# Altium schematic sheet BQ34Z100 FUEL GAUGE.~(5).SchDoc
size A3; SheetNumber: 13; SheetTotal: 14
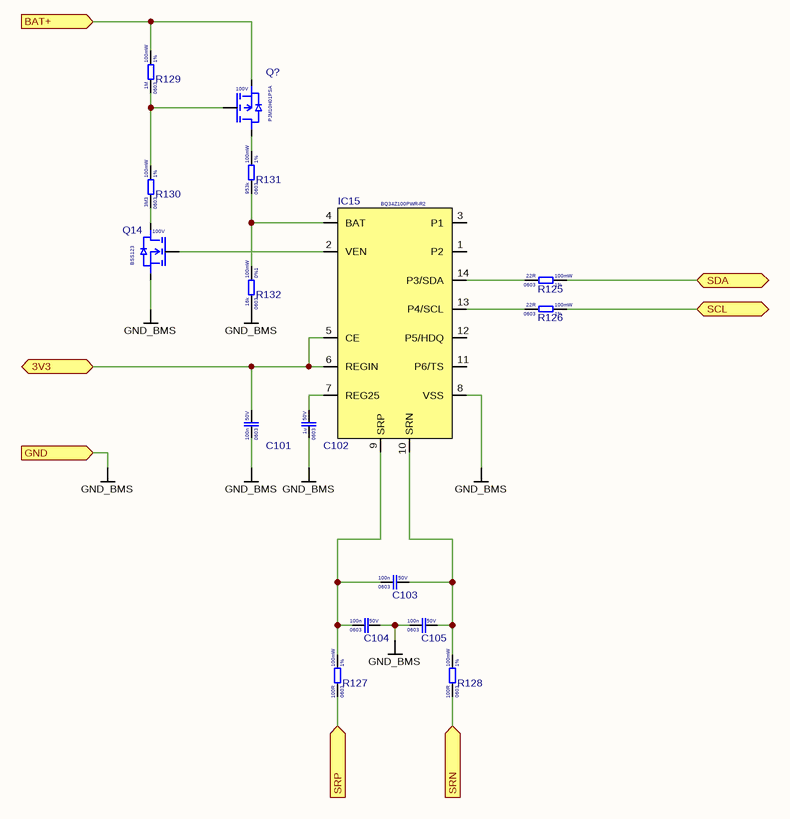
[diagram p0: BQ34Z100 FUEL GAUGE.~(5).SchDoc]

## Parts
C101  Voltage Rating: 50V  Case Code (Imperial): 0603  Capacitance: 100n  [CAP 0603]  (hidden comment: CC0603KRX7R9BB104)
C102  Voltage Rating: 50V  Case Code (Imperial): 0603  Capacitance: 1u  [CAP 0603]  (hidden comment: CL10A105KB8NNNC)
C103  Voltage Rating: 50V  Case Code (Imperial): 0603  Capacitance: 100n  [CAP 0603]  (hidden comment: CC0603KRX7R9BB104)
C104  Voltage Rating: 50V  Case Code (Imperial): 0603  Capacitance: 100n  [CAP 0603]  (hidden comment: CC0603KRX7R9BB104)
C105  Voltage Rating: 50V  Case Code (Imperial): 0603  Capacitance: 100n  [CAP 0603]  (hidden comment: CC0603KRX7R9BB104)
IC15  BQ34Z100PWR-R2  [TSSOP-14]
Q14  Voltage: 100V  [SOT-23 GSD]  (hidden comment: BSS123)
Q?  Voltage: 100V  [SOT-23 GSD]  (hidden comment: PJM10H01PSA)
R125  Resistance Tolerance: 1%  Resistance: 22R  Power Rating: 100mW  Case Code (Imperial): 0603  [RES_0603]  (hidden comment: 0603WAF220JT5E)
R126  Resistance Tolerance: 1%  Resistance: 22R  Power Rating: 100mW  Case Code (Imperial): 0603  [RES_0603]  (hidden comment: 0603WAF220JT5E)
R127  Resistance Tolerance: 1%  Resistance: 100R  Power Rating: 100mW  Case Code (Imperial): 0603  [RES_0603]  (hidden comment: 0603WAF1000T5E)
R128  Resistance Tolerance: 1%  Resistance: 100R  Power Rating: 100mW  Case Code (Imperial): 0603  [RES_0603]  (hidden comment: 0603WAF1000T5E)
R129  Resistance Tolerance: 1%  Resistance: 1M  Power Rating: 100mW  Case Code (Imperial): 0603  [RES_0603]  (hidden comment: 0603WAF1004T5E)
R130  Resistance Tolerance: 1%  Resistance: 3M3  Power Rating: 100mW  Case Code (Imperial): 0603  [RES_0603]  (hidden comment: 0603WAF3304T5E)
R131  Resistance Tolerance: 1%  Resistance: 953k  Power Rating: 100mW  Case Code (Imperial): 0603  [RES_0603]  (hidden comment: AC0603FR-07953KL)
R132  Resistance Tolerance: 0%1  Resistance: 16k  Power Rating: 100mW  Case Code (Imperial): 0603  [RES_0603]  (hidden comment: RT0603BRD0716KL)

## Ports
3V3 (bidir, see BMS[4C], 5V to 3V3 LDO[5B]), BAT+ (in, see BMS[4D], BAT+ to 5V1 STEP-DOWN[3B], BMS[1A], BQ76952 BMS[1A]), GND (in, see BMS[4D], 5V to 3V3 LDO[3B], BAT+ to 5V1 STEP-DOWN[3C], BQ76952 BMS[1D], MCU[1C]), SCL (bidir, see BMS[4C], BMS[8C], BQ76952 BMS[7C], MCU[1B]), SDA (bidir, see BMS[4C], BMS[8C], BQ76952 BMS[7C], MCU[1B]), SRN (in, see BMS[4D], BQ76952 BMS[5D]), SRP (in, see BMS[4D], BQ76952 BMS[5D])

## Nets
GND_BMS: C101.1 C102.1 C104.2 C105.1 IC15.8(VSS) Q14.S R132.1 ; port GND
3V3: C101.2 IC15.5(CE) IC15.6(REGIN) ; port 3V3
BAT+: Q?.S R129.2 ; port BAT+
SCL: R126.2 ; port SCL
SDA: R125.2 ; port SDA
SRN: R128.1 ; port SRN
SRP: R127.1 ; port SRP
NetC102_2: C102.2 IC15.7(REG25)
NetC103_1: C103.1 C104.1 IC15.9(SRP) R127.2
NetC103_2: C103.2 C105.2 IC15.10(SRN) R128.2
NetIC15_2: IC15.2(VEN) Q14.G
NetIC15_4: IC15.4(BAT) R131.1 R132.2
NetIC15_13: IC15.13(P4/SCL) R126.1
NetIC15_14: IC15.14(P3/SDA) R125.1
NetQ14_D: Q14.D R130.1
NetQ?_D: Q?.D R131.2
NetQ?_G: Q?.G R129.1 R130.2

Not connected (* = marked no-connect by the designer): IC15 1(P2) 3(P1) 11(P6/TS) 12(P5/HDQ)

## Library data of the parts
C101 C103-C105 = CC0603KRX7R9BB104: Cap 100nF 50V 0603 X7R; Manufacturer: Yageo
C102 = CL10A105KB8NNNC: Cap 1uF 50V 0603 X5R; Manufacturer: Samsung
IC15 = BQ34Z100PWR-R2: Fuel gauge; Manufacturer: Texas Instruments
Q14 = BSS123: Nmos 100V 170mA SOT-23; Manufacturer: hongjiacheng
Q? = PJM10H01PSA: Pmos 100V 1A 650mR SOT-23; Manufacturer: PJSEMI
R125 R126 = 0603WAF220JT5E: Res 22R 0603 1% 100mW 75V; Manufacturer: Uni-Royal
R127 R128 = 0603WAF1000T5E: Res 100R 0603 1% 100mW 75V; Manufacturer: Uni-Royal
R129 = 0603WAF1004T5E: Res 1M 0603 1% 100mW 75V; Manufacturer: Uni-Royal
R130 = 0603WAF3304T5E: Res 3M3 0603 1% 100mW 75V; Manufacturer: Uni-Royal
R131 = AC0603FR-07953KL: Res 953k 0603 1% 100mW 75V; Manufacturer: YAGEO
R132 = RT0603BRD0716KL: Res 16k 0603 0.1% 100mW 75V 25ppm; Manufacturer: YAGEO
